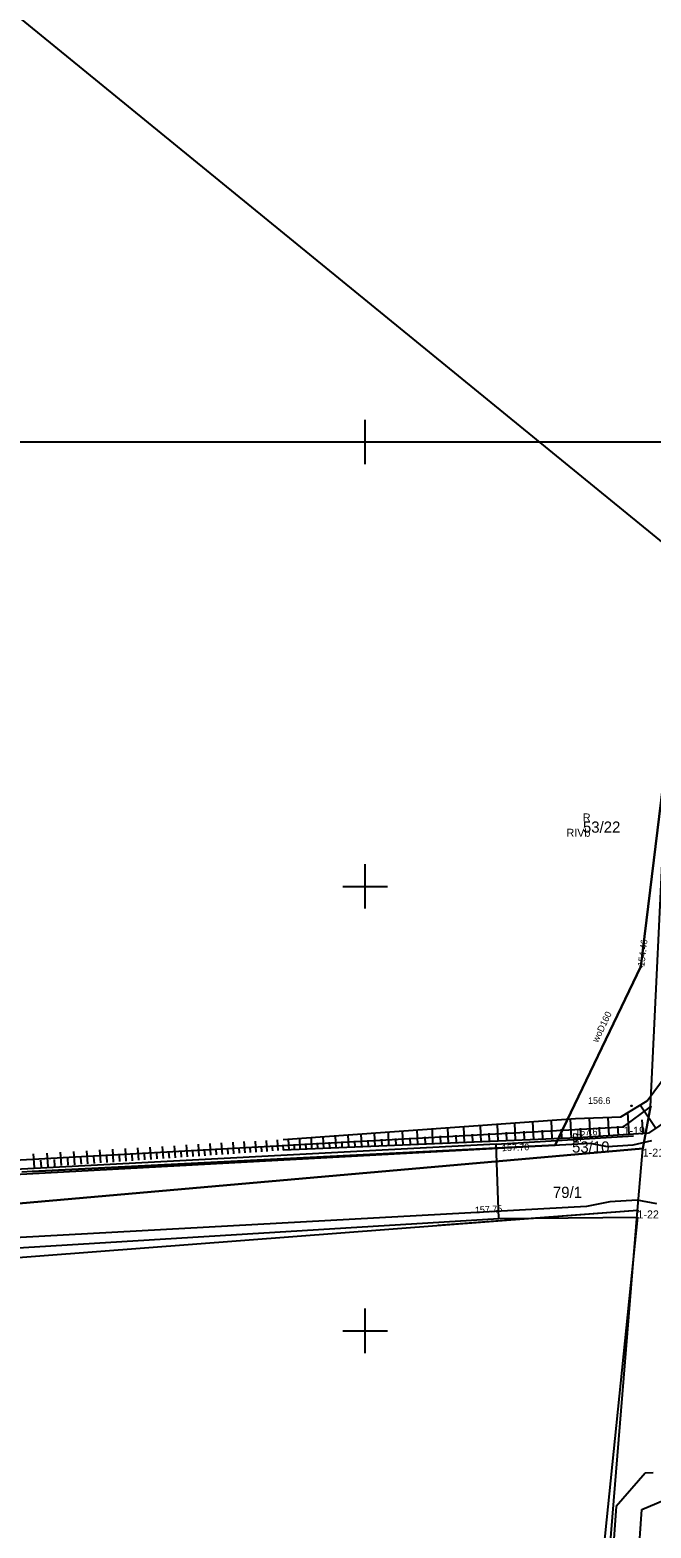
# Model space of a CAD drawing. Extents: x 5598798 to 5599616, y 5661498 to 5662453.
# Drawn here: x 5599112.3 to 5599182.2, y 5661877.8 to 5662046.3 of the extents above; entities that cross this region are included whole.
import ezdxf

# ---------------------------------------------------------------- set-up
doc = ezdxf.new("R2010")
doc.units = 0
for name, color, linetype in [('BUBZ_L_1', 7, 'Continuous'), ('Dzialki', 7, 'Continuous'), ('Kontury', 7, 'Continuous'), ('KTJZ_L_0', 7, 'Continuous'), ('KTKR_L_0', 7, 'Continuous'), ('KTOK_L_1', 7, 'Continuous'), ('KTOK_L_4', 7, 'Continuous'), ('Numery_dzialek', 7, 'Continuous'), ('Numery_konturow', 7, 'Continuous'), ('Numery_punktow', 7, 'Continuous'), ('Numery_uzytkow', 7, 'Continuous'), ('Podzial_sekcyjny_krzyze', 7, 'Continuous'), ('Podzial_sekcyjny_podstawowy', 7, 'Continuous'), ('PTRW_L_1', 7, 'Continuous'), ('Punkty', 7, 'Continuous'), ('RTPW_T_0', 7, 'Continuous'), ('RTPW_T_1', 7, 'Continuous'), ('SUPW_E_T_0', 7, 'Continuous'), ('SUPW_L_0', 7, 'Continuous'), ('SUTW_T_0', 7, 'Continuous'), ('Uzytki', 7, 'Continuous')]:
    doc.layers.add(name, color=color, linetype=linetype)

# ---------------------------------------------------------------- blocks, each defined once
blk = doc.blocks.new('GRO')
blk.add_circle((0, 0), 0.045)
blk = doc.blocks.new('2_RTPW02')
blk.add_circle((0, 0), 0.045)
blk = doc.blocks.new('2_RTPW01')
blk.add_circle((0, 0), 0.045)
blk = doc.blocks.new('4_SUPS01_08')
blk.add_circle((0, 0), 0.0625)

msp = doc.modelspace()

# ---------------------------------------------------------------- linework, layer by layer
at = {"layer": 'BUBZ_L_1'}
for p, q in [((5599181.74, 5661925.86), (5599183.88, 5661928.77)), ((5599178.75, 5661924.06), (5599181.74, 5661925.86)), ((5599173.65, 5661923.87), (5599178.75, 5661924.06)), ((5599175.36712, 5661921.787019), (5599175.224523, 5661923.928659)), ((5599177.462668, 5661921.926547), (5599177.324154, 5661924.00688)), ((5599179.722589, 5661922.077019), (5599179.558162, 5661924.546519)), ((5599182.688462, 5661922.77452), (5599180.928847, 5661925.371681)), ((5599185.25, 5661924.51), (5599181.87, 5661922.22)), ((5599140.75, 5661921.53), (5599173.65, 5661923.87)), ((5599151.117926, 5661920.74119), (5599151.054579, 5661922.262909)), ((5599152.67388, 5661920.805962), (5599152.608627, 5661922.37344)), ((5599154.276621, 5661920.872683), (5599154.209407, 5661922.487295)), ((5599155.927557, 5661920.94141), (5599155.858322, 5661922.604574)), ((5599157.628138, 5661921.012203), (5599157.55682, 5661922.725379)), ((5599159.379855, 5661921.085125), (5599159.306392, 5661922.849816)), ((5599161.184246, 5661921.16024), (5599161.108575, 5661922.977996)), ((5599163.042896, 5661921.237614), (5599162.964949, 5661923.11003)), ((5599164.957435, 5661921.317314), (5599164.877145, 5661923.246034)), ((5599165.936187, 5661921.358058), (5599165.895443, 5661922.33681)), ((5599166.929546, 5661921.399411), (5599166.846841, 5661923.386128)), ((5599167.937729, 5661921.441381), (5599167.895759, 5661922.449564)), ((5599168.960958, 5661921.483977), (5599168.875766, 5661923.530434)), ((5599169.999457, 5661921.527208), (5599169.956225, 5661922.565708)), ((5599171.053455, 5661921.571085), (5599170.965701, 5661923.67908)), ((5599172.123182, 5661921.615617), (5599172.07865, 5661922.685344)), ((5599173.208873, 5661921.660813), (5599173.118481, 5661923.832196)), ((5599174.2963, 5661921.715721), (5599174.223959, 5661922.802204)), ((5599176.422502, 5661921.85729), (5599176.352231, 5661922.912672)), ((5599178.487839, 5661921.994806), (5599178.41958, 5661923.019977)), ((5599181.291346, 5661922.181472), (5599181.186893, 5661923.750228)), ((5599124.516993, 5661919.184667), (5599124.41977, 5661920.587973)), ((5599125.908236, 5661919.281054), (5599125.812127, 5661920.668292)), ((5599127.28355, 5661919.376337), (5599127.188541, 5661920.747692)), ((5599128.643117, 5661919.47053), (5599128.549196, 5661920.826183)), ((5599129.987118, 5661919.563644), (5599129.894273, 5661920.903775)), ((5599131.315731, 5661919.655691), (5599131.223949, 5661920.980479)), ((5599132.629132, 5661919.746685), (5599132.5384, 5661921.056305)), ((5599133.927495, 5661919.836637), (5599133.837802, 5661921.131262)), ((5599135.210993, 5661919.925559), (5599135.122327, 5661921.205361)), ((5599135.84722, 5661919.969637), (5599135.803142, 5661920.605865)), ((5599136.479795, 5661920.013463), (5599136.392144, 5661921.278612)), ((5599137.108738, 5661920.057037), (5599137.065164, 5661920.68598)), ((5599137.734069, 5661920.10036), (5599137.647422, 5661921.351024)), ((5599138.355811, 5661920.143435), (5599138.312736, 5661920.765177)), ((5599138.973984, 5661920.186263), (5599138.888328, 5661921.422607)), ((5599139.588607, 5661920.228845), (5599139.546025, 5661920.843468)), ((5599140.199701, 5661920.271182), (5599140.115027, 5661921.493371)), ((5599173.91, 5661921.69), (5599140.76, 5661920.31)), ((5599140.808105, 5661920.312003), (5599140.782742, 5661920.921264)), ((5599141.426459, 5661920.337744), (5599141.374976, 5661921.574451)), ((5599142.054041, 5661920.36387), (5599142.027915, 5661920.991451)), ((5599142.690988, 5661920.390385), (5599142.637957, 5661921.66428)), ((5599143.337441, 5661920.417296), (5599143.31053, 5661921.063749)), ((5599143.993542, 5661920.444609), (5599143.938917, 5661921.75681)), ((5599144.659434, 5661920.472329), (5599144.631714, 5661921.138222)), ((5599145.335264, 5661920.500463), (5599145.278996, 5661921.852123)), ((5599146.02118, 5661920.529017), (5599145.992626, 5661921.214933)), ((5599146.717332, 5661920.557998), (5599146.659372, 5661921.950302)), ((5599147.423873, 5661920.58741), (5599147.394461, 5661921.293951)), ((5599148.140959, 5661920.617262), (5599148.081256, 5661922.051433)), ((5599148.868746, 5661920.647559), (5599148.838449, 5661921.375346)), ((5599149.607395, 5661920.678308), (5599149.545896, 5661922.155605)), ((5599150.357066, 5661920.709516), (5599150.325858, 5661921.459188)), ((5599151.890141, 5661920.773336), (5599151.857994, 5661921.545551)), ((5599153.469315, 5661920.839076), (5599153.436202, 5661921.634511)), ((5599155.095975, 5661920.906792), (5599155.061867, 5661921.726146)), ((5599156.77155, 5661920.976544), (5599156.736415, 5661921.820536)), ((5599158.497509, 5661921.048394), (5599158.461318, 5661921.917765)), ((5599160.275368, 5661921.122404), (5599160.238089, 5661922.017918)), ((5599162.106688, 5661921.19864), (5599162.068287, 5661922.121082)), ((5599163.993075, 5661921.277169), (5599163.95352, 5661922.227348)), ((5599181.87, 5661922.22), (5599173.91, 5661921.69)), ((5599112.791008, 5661918.372279), (5599112.684403, 5661919.911005)), ((5599113.555954, 5661918.425275), (5599113.502957, 5661919.190221)), ((5599114.316508, 5661918.477967), (5599114.211124, 5661919.999075)), ((5599115.072695, 5661918.530357), (5599115.020306, 5661919.286544)), ((5599115.824541, 5661918.582445), (5599115.720364, 5661920.086138)), ((5599116.572071, 5661918.634235), (5599116.520281, 5661919.381765)), ((5599117.315309, 5661918.685727), (5599117.212324, 5661920.172203)), ((5599118.05428, 5661918.736924), (5599118.003083, 5661919.475895)), ((5599118.789008, 5661918.787827), (5599118.687202, 5661920.257283)), ((5599119.519518, 5661918.838437), (5599119.468907, 5661919.568947)), ((5599120.245834, 5661918.888757), (5599120.145194, 5661920.341389)), ((5599120.96798, 5661918.938788), (5599120.917948, 5661919.660934)), ((5599121.685979, 5661918.988532), (5599121.586492, 5661920.424532)), ((5599122.399857, 5661919.03799), (5599122.350399, 5661919.751868)), ((5599123.109636, 5661919.087164), (5599123.011288, 5661920.506723)), ((5599123.81534, 5661919.136056), (5599123.766448, 5661919.84176)), ((5599125.214617, 5661919.233), (5599125.166285, 5661919.930624)), ((5599126.597873, 5661919.328833), (5599126.550094, 5661920.01847)), ((5599127.965291, 5661919.423569), (5599127.918059, 5661920.10531)), ((5599129.317053, 5661919.517221), (5599129.270362, 5661920.191156)), ((5599130.653337, 5661919.6098), (5599130.607181, 5661920.276019)), ((5599131.974322, 5661919.701319), (5599131.928694, 5661920.35991)), ((5599133.280183, 5661919.79179), (5599133.235077, 5661920.442841)), ((5599134.571091, 5661919.881226), (5599134.526502, 5661920.524822)), ((5599181.124984, 5661879.908151), (5599185.479134, 5661881.732747)), ((5599179.943143, 5661862.243239), (5599181.124984, 5661879.908151))]:
    msp.add_line(p, q, dxfattribs=at)
at = {"layer": 'Dzialki'}
for p, q in [((5599186.52, 5661986.2), (5599074.88, 5662077.34)), ((5599182.1, 5661925.2), (5599183.8, 5661960.37)), ((5599179.08, 5661922.96), (5599182.1, 5661925.2)), ((5599182.1, 5661925.2), (5599181.23, 5661920.49)), ((5599095.27, 5661918.37), (5599179.08, 5661922.96)), ((5599181.23, 5661920.49), (5599075.65, 5661911.2)), ((5599180.64, 5661913.54), (5599181.23, 5661920.49)), ((5599180.64, 5661913.54), (5599084.84, 5661906.2)), ((5599170.63, 5661790.83), (5599180.64, 5661913.54))]:
    msp.add_line(p, q, dxfattribs=at)
at = {"layer": 'Kontury'}
for p, q in [((5599186.52, 5661986.2), (5599074.88, 5662077.34)), ((5599182.1, 5661925.2), (5599183.8, 5661960.37)), ((5599181.23, 5661920.49), (5599182.1, 5661925.2)), ((5599075.65, 5661911.2), (5599181.23, 5661920.49))]:
    msp.add_line(p, q, dxfattribs=at)
at = {"layer": 'KTJZ_L_0'}
for p, q in [((5599098.3, 5661916.91), (5599175.3, 5661921.09)), ((5599175.3, 5661921.09), (5599177.24, 5661920.73)), ((5599177.24, 5661920.73), (5599180.16, 5661920.93)), ((5599180.16, 5661920.93), (5599182.24, 5661921.42)), ((5599174.91, 5661913.97), (5599099.89, 5661909.87)), ((5599177.54, 5661914.51), (5599174.91, 5661913.97)), ((5599180.59, 5661914.71), (5599177.54, 5661914.51)), ((5599182.82, 5661914.28), (5599180.59, 5661914.71))]:
    msp.add_line(p, q, dxfattribs=at)
at = {"layer": 'KTKR_L_0'}
for p, q in [((5599098.3, 5661916.91), (5599175.3, 5661921.09)), ((5599175.3, 5661921.09), (5599177.24, 5661920.73)), ((5599177.24, 5661920.73), (5599180.16, 5661920.93)), ((5599180.16, 5661920.93), (5599182.24, 5661921.42)), ((5599174.91, 5661913.97), (5599099.89, 5661909.87)), ((5599177.54, 5661914.51), (5599174.91, 5661913.97)), ((5599180.59, 5661914.71), (5599177.54, 5661914.51)), ((5599182.82, 5661914.28), (5599180.59, 5661914.71))]:
    msp.add_line(p, q, dxfattribs=at)
at = {"layer": 'KTOK_L_1'}
msp.add_line((5599165.02, 5661912.62), (5599164.73, 5661920.98), dxfattribs=at)
at = {"layer": 'KTOK_L_4'}
for p, q in [((5599164.73, 5661920.98), (5599101.3, 5661917.68)), ((5599164.73, 5661920.98), (5599180.19, 5661921.95)), ((5599099.97, 5661908.66), (5599165.02, 5661912.62)), ((5599165.02, 5661912.62), (5599180.63, 5661912.77)), ((5599180.63, 5661912.77), (5599176.428243, 5661871.738043))]:
    msp.add_line(p, q, dxfattribs=at)
at = {"layer": 'Podzial_sekcyjny_krzyze'}
for p, q in [((5599150, 5661997.5), (5599150, 5662002.5)), ((5599147.5, 5662000), (5599152.5, 5662000)), ((5599150, 5661947.5), (5599150, 5661952.5)), ((5599147.5, 5661950), (5599152.5, 5661950)), ((5599150, 5661897.5), (5599150, 5661902.5)), ((5599147.5, 5661900), (5599152.5, 5661900))]:
    msp.add_line(p, q, dxfattribs=at)
at = {"layer": 'Podzial_sekcyjny_podstawowy'}
msp.add_line((5598800, 5662000), (5599200, 5662000), dxfattribs=at)
at = {"layer": 'PTRW_L_1'}
for p, q in [((5599181.499939, 5661883.990835), (5599178.24884, 5661880.242119)), ((5599182.39565, 5661884.02401), (5599181.499939, 5661883.990835)), ((5599178.24884, 5661880.242119), (5599175.395835, 5661839.501206)), ((5599181.124984, 5661879.908151), (5599185.479134, 5661881.732747)), ((5599179.943143, 5661862.243239), (5599181.124984, 5661879.908151))]:
    msp.add_line(p, q, dxfattribs=at)
at = {"layer": 'SUPW_L_0'}
for p, q in [((5599181.036243, 5661940.982154), (5599189.084637, 5662007.286789)), ((5599189.084637, 5662007.286789), (5599181.036243, 5661940.982154)), ((5599171.38228, 5661920.89296), (5599181.036243, 5661940.982154)), ((5599181.036243, 5661940.982154), (5599171.38228, 5661920.89296)), ((5599112.517084, 5661917.916406), (5599171.38228, 5661920.89296)), ((5599171.38228, 5661920.89296), (5599112.517084, 5661917.916406)), ((5599112.517084, 5661917.916406), (5599111.350794, 5661917.843512))]:
    msp.add_line(p, q, dxfattribs=at)
at = {"layer": 'Uzytki'}
for p, q in [((5599186.52, 5661986.2), (5599074.88, 5662077.34)), ((5599182.1, 5661925.2), (5599183.8, 5661960.37)), ((5599179.08, 5661922.96), (5599182.1, 5661925.2)), ((5599181.23, 5661920.49), (5599182.1, 5661925.2)), ((5599095.27, 5661918.37), (5599179.08, 5661922.96)), ((5599075.65, 5661911.2), (5599181.23, 5661920.49)), ((5599180.64, 5661913.54), (5599158.22, 5661911.83)), ((5599170.63, 5661790.83), (5599180.64, 5661913.54))]:
    msp.add_line(p, q, dxfattribs=at)

# ---------------------------------------------------------------- block references
at = {"layer": 'Punkty'}
for p in [(5599182.1, 5661925.2), (5599179.08, 5661922.96), (5599181.23, 5661920.49), (5599180.64, 5661913.54)]:
    msp.add_blockref('GRO', p, dxfattribs=at)
at = {"layer": 'RTPW_T_0'}
msp.add_blockref('2_RTPW01', (5599179.972621, 5661925.316638), dxfattribs=at)
at = {"layer": 'RTPW_T_0', "rotation": -3.0000000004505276e-06}
msp.add_blockref('2_RTPW01', (5599173.91, 5661921.69), dxfattribs=at)
at = {"layer": 'RTPW_T_1'}
for p in [(5599164.64, 5661920.57), (5599164.82, 5661913.44)]:
    msp.add_blockref('2_RTPW02', p, dxfattribs=at)
at = {"layer": 'SUTW_T_0'}
msp.add_blockref('4_SUPS01_08', (5599181.036243, 5661940.982154), dxfattribs=at)

# ---------------------------------------------------------------- texts
at = {"layer": 'Numery_dzialek'}
for s, p in [('53/22', (5599174.501575, 5661956.037008)), ('53/10', (5599173.274387, 5661920.048598)), ('79/1', (5599171.121437, 5661914.947756))]:
    msp.add_text(s, height=1.26, dxfattribs=at).set_placement(p)
at = {"layer": 'Numery_konturow'}
msp.add_text('RIVb', height=0.9, dxfattribs=at).set_placement((5599172.6627, 5661955.578645))
at = {"layer": 'Numery_punktow'}
for s, p in [('1-19', (5599179.08, 5661922.06)), ('1-21', (5599181.23, 5661919.59)), ('1-22', (5599180.64, 5661912.64))]:
    msp.add_text(s, height=0.9, dxfattribs=at).set_placement(p)
at = {"layer": 'Numery_uzytkow'}
for s, p in [('R', (5599174.501575, 5661957.297008)), ('Br', (5599173.274387, 5661921.308598))]:
    msp.add_text(s, height=0.9, dxfattribs=at).set_placement(p)
at = {"layer": 'RTPW_T_0'}
msp.add_text('156.6', height=0.75, rotation=359.858529, dxfattribs=at).set_placement((5599175.081874, 5661925.533102))
msp.add_text('157.6', height=0.75, dxfattribs=at).set_placement((5599173.63241, 5661922.00729))
at = {"layer": 'RTPW_T_1'}
for s, rotation, p in [('157.70', 2.233271, (5599165.409477, 5661920.198133)), ('157.75', 3.250586, (5599162.376835, 5661913.205569))]:
    msp.add_text(s, height=0.75, rotation=rotation, dxfattribs=at).set_placement(p)
at = {"layer": 'SUPW_E_T_0'}
msp.add_text('woD160', height=0.75, rotation=64.333159, dxfattribs=at).set_placement((5599176.184628, 5661932.37623))
at = {"layer": 'SUTW_T_0'}
msp.add_text('154.46', height=0.75, rotation=83.078996, dxfattribs=at).set_placement((5599181.40851, 5661940.936966))

doc.saveas('drawing.dxf')
